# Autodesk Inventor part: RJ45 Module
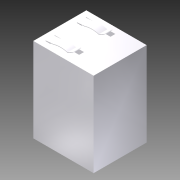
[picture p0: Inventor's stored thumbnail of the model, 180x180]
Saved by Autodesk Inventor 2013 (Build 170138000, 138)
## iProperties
Company: Autodesk Inc.
Created: 2005-11
Part Number: RJ45 Module
Document SubType Name: Modeling
Designer: Autodesk Inc.
Density: 1 g/cm^3
Mass: 13.2374 g
Surface Area: 91.9014 cm^2
Volume: 13.2374 cm^3
Material: Allgemein
Title: Personal Computer
Author: Autodesk Inc.
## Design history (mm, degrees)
sketch "Sketch1"
  geometry: L1 (0, 15.4)-(0, -15.4) reference; L2 (-5, 0)-(30, 0) reference; L3 (0, 11)-(25, 11); L4 (25, 11)-(25, -11); L5 (25, -11)-(0, -11); L6 (0, -11)-(0, 11)
  constraints: 8 end point, 2 parallel, 1 horizontal, 1 perpendicular, 1 point on line, 1 other
  dimensions: "d0" = 22 distance of L3.end L4.end; "d1" = 25 distance of L3.start L3.end
extrude "Extrusion1" new body sketch "Sketch1" distance "d2" = 35; taper "d3" = 0 deg
sketch "Sketch2"
  geometry: L1 (0, 0)-(0, 22) reference; L2 (-7, 11)-(42, 11) reference; L3 (4, 18.5)-(10, 18.5); L4 (10, 18.5)-(10, 3.5); L5 (10, 3.5)-(4, 3.5); L6 (4, 3.5)-(4, 18.5); L7 (12.5, 18.5)-(18.5, 18.5); L8 (18.5, 18.5)-(18.5, 3.5); L9 (18.5, 3.5)-(12.5, 3.5); L10 (12.5, 3.5)-(12.5, 18.5); L11 (20.5, 18.5)-(27.5, 18.5); L12 (27.5, 18.5)-(27.5, 3.5); L13 (27.5, 3.5)-(20.5, 3.5); L14 (20.5, 3.5)-(20.5, 18.5); L15 (27.5, 17)-(31.5, 17); L16 (31.5, 17)-(31.5, 5); L17 (31.5, 5)-(27.5, 5); L18 (27.5, 5)-(27.5, 17)
  constraints: 32 end point, 8 parallel, 5 collinear, 4 horizontal, 4 perpendicular, 1 point on line, 2 other
  dimensions: "d4" = 4 distance between parallel lines of L1 L6; "d5" = 15 distance of L5.end L3.start; "d6" = 2.5 distance between parallel lines of L10 L4; "d7" = 6 distance of L4.end L5.end; "d8" = 11 distance between parallel lines of L16 L14; "d9" = 2 distance between parallel lines of L8 L14; "d10" = 7 distance of L11.start L11.end; "d11" = 12 distance of L15.end L16.end
extrude "Extrusion2" cut sketch "Sketch2" distance "d12" = 20; taper "d13" = 0 deg
sketch "Sketch3"
  geometry: L1 (10, 3.5)-(10, 18.5) reference; L2 (9, 18)-(7.5, 18); L3 (7.5, 18)-(7.5, 4); L4 (7.5, 4)-(9, 4); L5 (9, 4)-(9, 18); L6 (17.5, 18)-(16, 18); L7 (16, 18)-(16, 4); L8 (16, 4)-(17.5, 4); L9 (17.5, 4)-(17.5, 18); L10 (12.5, 18.5)-(12.5, 3.5) reference; L11 (12.5, 3.5)-(18.5, 3.5) reference; L12 (18.5, 3.5)-(18.5, 18.5) reference; L13 (18.5, 18.5)-(12.5, 18.5) reference; L14 (-7, 11)-(42, 11) reference
  constraints: 16 end point, 4 parallel, 2 equal length, 2 horizontal, 2 perpendicular, 2 other
  dimensions: "d14" = 1.5 distance of L2.start L2.end; "d15" = 1 distance between parallel lines of L1 L5; "d16" = 1 distance between parallel lines of L12 L9 (= d15); "d17" = 14 distance of L2.end L3.end
extrude "Extrusion3" join sketch "Sketch3" distance "d18" = 18; taper "d19" = 0 deg
sketch "Sketch4"
  geometry: L1 (-20, 27.5)-(-20, 20.5) reference; L2 (0, 20.5)-(-20, 20.5) reference; L3 (-20, 23)-(-2, 20.5); L4 (0, 0)-(0, 35) reference; 2 further points
  constraints: 2 coincident, 2 end point, 2 point on line
  dimensions: "d20" = 2 distance from line of L4 point (-2, 20.5); "d21" = 2.5 distance from line of L2 L3.start
extrude "Extrusion4" join sketch "Sketch4" stored distance "d22" = 10; taper "d23" = 0 deg
sketch "Sketch5"
  geometry: L1 (20.5, 16)-(23, 16) reference; L2 (23, 16)-(23, 6) reference; L3 (20.5, 3.5)-(20.5, 18.5) reference; L4 (20.5, 15.8)-(23, 15.8); L5 (23, 15.8)-(23, 15.3); L6 (23, 15.3)-(20.5, 15.3); L7 (20.5, 15.3)-(20.5, 15.8)
  constraints: 8 end point, 2 parallel, 2 point on line, 1 horizontal, 1 perpendicular
  dimensions: "d24" = 0.2 distance between parallel lines of L4 L1; "d25" = 0.5 distance between parallel lines of L6 L4
extrude "Extrusion5" cut sketch "Sketch5" stored distance "d26" = 14; taper "d27" = 0 deg
pattern_linear "Rectangular Pattern1" dims "d30" = 0.7
sketch "Sketch6"
  geometry: L1 (0, 11)-(25, 11) reference; L2 (0, -11)-(0, 11) reference; L3 (2.5, 8.5)-(14.5, 8.5); L4 (14.5, 8.5)-(14.5, 4.5); L5 (14.5, 4.5)-(2.5, 4.5); L6 (2.5, 4.5)-(2.5, 8.5)
  constraints: 8 end point, 2 parallel, 1 horizontal, 1 perpendicular
  dimensions: "d31" = 2.5 distance between parallel lines of L1 L3; "d32" = 12 distance of L3.start L3.end; "d33" = 4 distance of L3.end L4.end; "d34" = 2.5 distance between parallel lines of L2 L6
extrude "Extrusion6" cut sketch "Sketch6" distance "d35" = 2; taper "d36" = 0 deg
workplane "Work Plane1"
sketch "Sketch7"
  geometry: L1 (0, 2)-(0, 0) reference; L2 (0, 2)-(3.048, 2.267); L3 (8.95, 2.285)-(11, 3.241); L4 (0, 1.799)-(3.087, 2.069); L5 (8.965, 2.071)-(11.085, 3.06); L6 (11, 3.241)-(11.085, 3.06); L7 (0, 2)-(0, 1.799); A1 r 10 centre (6.029, -7.279) between (8.95, 2.285) and (3.048, 2.267); A2 r 9.8 centre (6.029, -7.279) between (8.965, 2.071) and (3.087, 2.069)
  constraints: 13 end point, 4 point on circle, 2 centre point, 1 perpendicular, 1 point on line, 1 other
  dimensions: "d37" = 11 distance from line of L1 L3.end; "d38" = 95 deg angle of L1 L2; "d39" = 10 radius of A1; "d40" = 65 deg angle of L1 L3; "d41" = 0.2 distance between parallel lines of L4 L2
extrude "Extrusion7" join sketch "Sketch7" stored distance "d42" = 3.5; taper "d43" = 0 deg
mirror "Mirror1"
body "Solid1"
node "Projected Loop1"
